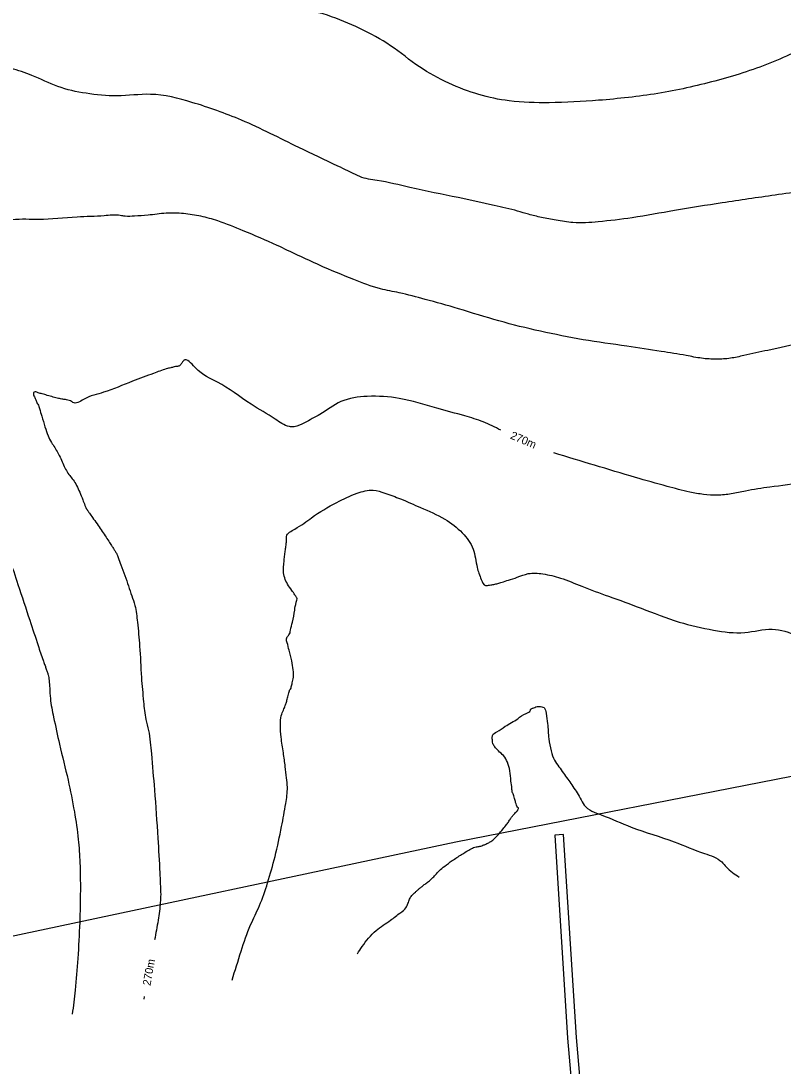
# Model space of a CAD drawing. Extents: x -478495 to -472450, y -1118050 to -1113745.
# Drawn here: x -474676.7 to -474505.2, y -1116040.4 to -1115805.4 of the extents above; entities that cross this region are included whole.
import ezdxf

# ---------------------------------------------------------------- set-up
doc = ezdxf.new("R2010")
doc.units = 0
for name, color, linetype in [('hranice kú', 7, 'Continuous'), ('ObPÚ', 7, 'Continuous'), ('vodní plochy', 7, 'Continuous'), ('Vrstevnice_hlavni', 7, 'Continuous'), ('Vrstevnice_popis', 7, 'Continuous'), ('Vrstevnice_vedlejsi', 7, 'Continuous')]:
    doc.layers.add(name, color=color, linetype=linetype)

msp = doc.modelspace()

# ---------------------------------------------------------------- linework, layer by layer
at = {"layer": 'hranice kú'}
for p, q in [((-474578.81, -1115989.99), (-474391.43, -1115953.34)), ((-474709.58, -1116017.74), (-474578.81, -1115989.99))]:
    msp.add_line(p, q, dxfattribs=at)
at = {"layer": 'ObPÚ'}
for p, q in [((-474578.81, -1115989.99), (-474391.43, -1115953.34)), ((-474709.58, -1116017.74), (-474578.81, -1115989.99))]:
    msp.add_line(p, q, dxfattribs=at)
at = {"layer": 'vodní plochy'}
msp.add_line((-474554.56, -1115988.35), (-474556.55, -1115988.48), dxfattribs=at)
for points in [[(-474556.55, -1115988.48), (-474553.66, -1116034.16)], [(-474529.71, -1116266.12), (-474535.81, -1116214.06), (-474540.64, -1116167.48), (-474541.99, -1116137.5), (-474545.48, -1116104.98), (-474551.66, -1116034.01), (-474554.56, -1115988.35)], [(-474553.66, -1116034.16), (-474547.47, -1116105.17), (-474543.99, -1116137.65), (-474542.64, -1116167.63), (-474537.8, -1116214.28), (-474531.83, -1116265.2)]]:
    msp.add_lwpolyline(points, dxfattribs=at)
at = {"layer": 'Vrstevnice_hlavni'}
msp.add_line((-474648.99, -1116025.33), (-474648.89, -1116024.79), dxfattribs=at)
for points in [[(-474353.29, -1115910.1), (-474357.76, -1115907), (-474363.58, -1115903.14), (-474372.98, -1115896.97), (-474385.95, -1115888.49), (-474394.72, -1115882.73), (-474399.29, -1115879.71), (-474399.64, -1115879.42), (-474399.97, -1115879.33), (-474400.28, -1115879.42), (-474400.55, -1115879.71), (-474401.05, -1115880.31), (-474401.76, -1115881.21), (-474402.7, -1115882.42), (-474405.92, -1115887.27), (-474411.43, -1115895.76), (-474419.22, -1115907.88), (-474425.86, -1115917.02), (-474431.34, -1115923.19), (-474435.67, -1115926.38), (-474439.9, -1115927.44), (-474444.04, -1115926.38), (-474448.08, -1115923.19), (-474453.87, -1115919.56), (-474461.41, -1115915.5), (-474470.71, -1115911.01), (-474480.28, -1115908.45), (-474490.15, -1115907.82), (-474500.29, -1115909.13), (-474508.12, -1115910.22), (-474513.62, -1115911.09), (-474516.81, -1115911.75), (-474519.96, -1115912.01), (-474523.07, -1115911.86), (-474526.15, -1115911.32), (-474531.26, -1115910.04), (-474538.41, -1115908.02), (-474556.79, -1115902.51)], [(-474568.71, -1115897.41), (-474572.64, -1115895.54), (-474576.77, -1115894.2), (-474583.07, -1115892.45), (-474591.54, -1115890.28), (-474598.74, -1115889.8), (-474604.7, -1115890.99), (-474609.4, -1115893.85), (-474612.89, -1115895.74), (-474615.18, -1115896.66), (-474616.27, -1115896.61), (-474619.51, -1115894.92), (-474624.89, -1115891.58), (-474632.42, -1115886.61), (-474637.48, -1115883.33), (-474640.07, -1115881.75), (-474640.18, -1115881.86), (-474640.33, -1115882.05), (-474640.51, -1115882.31), (-474640.73, -1115882.66), (-474640.99, -1115882.9), (-474641.29, -1115883.04), (-474641.64, -1115883.07), (-474642.2, -1115883.18), (-474642.99, -1115883.37), (-474643.99, -1115883.63), (-474646.84, -1115884.63), (-474651.55, -1115886.39), (-474658.1, -1115888.89), (-474662.59, -1115890.48), (-474664.99, -1115891.16), (-474665.32, -1115890.92), (-474665.81, -1115890.73), (-474666.45, -1115890.57), (-474667.26, -1115890.45), (-474668.24, -1115890.25), (-474669.42, -1115889.95), (-474670.78, -1115889.57), (-474671.92, -1115889.24), (-474672.82, -1115888.99), (-474673.5, -1115888.79), (-474673.84, -1115888.94), (-474673.83, -1115889.44), (-474673.49, -1115890.29), (-474673.22, -1115890.94), (-474673, -1115891.37), (-474672.85, -1115891.59), (-474672.51, -1115892.55), (-474671.99, -1115894.24), (-474671.28, -1115896.67), (-474670.56, -1115898.65), (-474669.83, -1115900.18), (-474669.09, -1115901.27), (-474668.4, -1115902.47), (-474667.74, -1115903.78), (-474667.12, -1115905.21), (-474666.45, -1115906.49), (-474665.72, -1115907.61), (-474664.93, -1115908.58), (-474664.18, -1115909.82), (-474663.46, -1115911.32), (-474662.77, -1115913.09), (-474662.29, -1115914.31), (-474662.01, -1115914.99), (-474661.93, -1115915.12), (-474661.85, -1115915.24), (-474661.77, -1115915.36), (-474661.68, -1115915.48), (-474661.29, -1115916.04), (-474660.58, -1115917.04), (-474659.56, -1115918.47), (-474658.61, -1115919.84), (-474657.73, -1115921.15), (-474656.92, -1115922.4), (-474656.31, -1115923.34), (-474655.89, -1115923.98), (-474655.67, -1115924.32), (-474655.48, -1115924.61), (-474655.32, -1115924.88), (-474655.2, -1115925.09), (-474654.82, -1115926.04), (-474654.19, -1115927.71), (-474653.3, -1115930.11), (-474652.48, -1115932.43), (-474651.74, -1115934.66), (-474651.05, -1115936.81), (-474650.47, -1115940.58), (-474649.97, -1115945.97), (-474649.57, -1115952.99), (-474649.1, -1115958.48), (-474648.57, -1115962.46), (-474647.98, -1115964.93), (-474647.34, -1115970.19), (-474646.64, -1115978.26), (-474645.89, -1115989.13), (-474645.42, -1115996.98), (-474645.23, -1116001.81)], [(-474645.23, -1116001.81), (-474645.33, -1116003.61), (-474645.52, -1116005.55), (-474645.82, -1116007.62), (-474646.61, -1116012.03)]]:
    msp.add_spline(points, degree=3, dxfattribs=at)
at = {"layer": 'Vrstevnice_vedlejsi'}
for points in [[(-474307.19, -1115713.78), (-474307.99, -1115713.91), (-474308.82, -1115714.23), (-474309.67, -1115714.76), (-474310.56, -1115715.49), (-474311.65, -1115716.4), (-474312.94, -1115717.49), (-474314.45, -1115718.76), (-474316.08, -1115719.99), (-474317.84, -1115721.19), (-474319.73, -1115722.34), (-474321.15, -1115723.17), (-474322.12, -1115723.66), (-474322.64, -1115723.82), (-474323.08, -1115724.06), (-474323.44, -1115724.38), (-474323.73, -1115724.79), (-474326.4, -1115725.43), (-474331.46, -1115726.31), (-474338.91, -1115727.42), (-474345.39, -1115728.27), (-474350.91, -1115728.88), (-474355.45, -1115729.23), (-474360.11, -1115731.22), (-474364.87, -1115734.85), (-474369.73, -1115740.13), (-474374.74, -1115745.26), (-474379.87, -1115750.27), (-474385.15, -1115755.13), (-474389.04, -1115759.06), (-474391.56, -1115762.05), (-474392.7, -1115764.11), (-474394.15, -1115766.16), (-474395.89, -1115768.21), (-474397.95, -1115770.27), (-474400.91, -1115771.86), (-474404.79, -1115773), (-474409.58, -1115773.69), (-474415.62, -1115774.92), (-474422.92, -1115776.7), (-474431.46, -1115779.03), (-474438.67, -1115781.14), (-474444.56, -1115783.02), (-474449.11, -1115784.68), (-474454.43, -1115787.3), (-474460.5, -1115790.89), (-474467.34, -1115795.44), (-474472.23, -1115798.79), (-474475.19, -1115800.92), (-474476.22, -1115801.84), (-474477.2, -1115802.56), (-474478.16, -1115803.09), (-474479.08, -1115803.42), (-474480.18, -1115803.71), (-474481.46, -1115803.96), (-474482.92, -1115804.16), (-474487.85, -1115806.05), (-474496.25, -1115809.62), (-474508.12, -1115814.87), (-474520.49, -1115818.88), (-474533.33, -1115821.67), (-474546.67, -1115823.22), (-474557.83, -1115823.77), (-474566.83, -1115823.34), (-474573.65, -1115821.91), (-474580.37, -1115819.36), (-474586.99, -1115815.71), (-474593.49, -1115810.94), (-474600.4, -1115807.07), (-474607.71, -1115804.11), (-474615.41, -1115802.05), (-474622.42, -1115800.42), (-474628.74, -1115799.21), (-474634.37, -1115798.42), (-474641.58, -1115797.17), (-474650.36, -1115795.45), (-474660.72, -1115793.27), (-474668.62, -1115791.35), (-474674.06, -1115789.7), (-474677.03, -1115788.3), (-474679.71, -1115787.15), (-474682.1, -1115786.24), (-474684.19, -1115785.57), (-474688.05, -1115785.01), (-474693.67, -1115784.55), (-474701.05, -1115784.2), (-474706.07, -1115783.9), (-474708.75, -1115783.67), (-474709.08, -1115783.5), (-474709.77, -1115783.43), (-474710.83, -1115783.48), (-474712.26, -1115783.64), (-474713.28, -1115783.74), (-474713.9, -1115783.78), (-474714.11, -1115783.76), (-474714.62, -1115783.69), (-474715.41, -1115783.58)], [(-474405.5, -1115810.13), (-474411, -1115813.31), (-474417.27, -1115815.96), (-474424.33, -1115818.06), (-474432.17, -1115819.63), (-474438.49, -1115821.66), (-474443.3, -1115824.16), (-474446.6, -1115827.13), (-474451.88, -1115830.21), (-474459.14, -1115833.4), (-474468.37, -1115836.7), (-474474.71, -1115838.99), (-474478.15, -1115840.26), (-474478.69, -1115840.51), (-474479.14, -1115840.68), (-474479.49, -1115840.76), (-474479.74, -1115840.76), (-474480.02, -1115840.77), (-474480.32, -1115840.82), (-474480.64, -1115840.89), (-474485.19, -1115841.53), (-474493.97, -1115842.75), (-474506.98, -1115844.55), (-474518.85, -1115846.29), (-474529.57, -1115847.99), (-474539.14, -1115849.64), (-474546.77, -1115850.55), (-474552.47, -1115850.73), (-474556.24, -1115850.16), (-474559.57, -1115849.54), (-474562.46, -1115848.86), (-474564.92, -1115848.12), (-474570.19, -1115846.87), (-474578.26, -1115845.11), (-474589.13, -1115842.83), (-474596.51, -1115841.25), (-474600.4, -1115840.37), (-474600.8, -1115840.19), (-474605.37, -1115838.01), (-474614.13, -1115833.84), (-474627.07, -1115827.68), (-474638.2, -1115823.69), (-474647.53, -1115821.88), (-474655.07, -1115822.24), (-474662.02, -1115821.65), (-474668.4, -1115820.11), (-474674.2, -1115817.62), (-474678.98, -1115816.02), (-474682.76, -1115815.29), (-474685.51, -1115815.44), (-474687.88, -1115815.58), (-474689.86, -1115815.71), (-474691.46, -1115815.83), (-474693.42, -1115816), (-474695.74, -1115816.22), (-474698.43, -1115816.49), (-474700.66, -1115816.67), (-474702.41, -1115816.78), (-474703.71, -1115816.82), (-474704.75, -1115816.93), (-474705.55, -1115817.14), (-474706.1, -1115817.42), (-474706.5, -1115817.63), (-474706.77, -1115817.77), (-474706.9, -1115817.82), (-474707.07, -1115817.94), (-474707.29, -1115818.12), (-474707.55, -1115818.35), (-474707.99, -1115818.69), (-474708.63, -1115819.11), (-474709.46, -1115819.64), (-474710.11, -1115819.92), (-474710.58, -1115819.96), (-474710.88, -1115819.75), (-474711.12, -1115819.56), (-474711.3, -1115819.42), (-474711.41, -1115819.3), (-474711.61, -1115818.94), (-474711.92, -1115818.33), (-474712.31, -1115817.48), (-474712.71, -1115816.64), (-474713.12, -1115815.83), (-474713.53, -1115815.03), (-474713.9, -1115814.35), (-474714.23, -1115813.79), (-474714.54, -1115813.33), (-474714.81, -1115812.86), (-474715.06, -1115812.38), (-474715.28, -1115811.88), (-474715.67, -1115811.15), (-474716.23, -1115810.18), (-474716.96, -1115808.98), (-474717.48, -1115808.13), (-474717.78, -1115807.64), (-474717.86, -1115807.51), (-474717.98, -1115807.32), (-474718.11, -1115807.08)], [(-474209.03, -1115951.03), (-474211.31, -1115950.17), (-474219.22, -1115947.13), (-474229.61, -1115943.09), (-474237.42, -1115939.16), (-474242.66, -1115935.36), (-474245.32, -1115931.67), (-474248.92, -1115928.32), (-474253.48, -1115925.32), (-474258.98, -1115922.66), (-474263.71, -1115920.22), (-474267.65, -1115917.99), (-474270.81, -1115915.98), (-474273.59, -1115914.5), (-474275.98, -1115913.57), (-474277.99, -1115913.16), (-474281.05, -1115911.98), (-474285.17, -1115910.01), (-474290.34, -1115907.25), (-474296.51, -1115904.05), (-474303.67, -1115900.41), (-474311.84, -1115896.33), (-474318.15, -1115893.11), (-474322.6, -1115890.76), (-474325.2, -1115889.28), (-474328.18, -1115887.42), (-474331.54, -1115885.2), (-474335.3, -1115882.6), (-474339.21, -1115879.96), (-474343.3, -1115877.27), (-474347.55, -1115874.53), (-474351.29, -1115870.13), (-474354.53, -1115864.06), (-474357.27, -1115856.31), (-474360.52, -1115850.2), (-474364.29, -1115845.71), (-474368.57, -1115842.86), (-474374.44, -1115840.32), (-474381.91, -1115838.09), (-474390.95, -1115836.19), (-474398.08, -1115835.56), (-474403.29, -1115836.19), (-474406.58, -1115838.09), (-474412.12, -1115842.87), (-474419.91, -1115850.52), (-474429.96, -1115861.04), (-474437.29, -1115868.36), (-474441.91, -1115872.47), (-474443.81, -1115873.38), (-474448.89, -1115873.86), (-474457.14, -1115873.93), (-474468.57, -1115873.57), (-474479.64, -1115874.09), (-474490.34, -1115875.48), (-474500.68, -1115877.74), (-474508.57, -1115879.45), (-474514.01, -1115880.62), (-474517.01, -1115881.23), (-474520.17, -1115881.44), (-474523.49, -1115881.23), (-474526.98, -1115880.62), (-474532.59, -1115879.71), (-474540.32, -1115878.52), (-474550.16, -1115877.05), (-474559.76, -1115875.15), (-474569.12, -1115872.83), (-474578.24, -1115870.1), (-474585.73, -1115867.98), (-474591.58, -1115866.48)], [(-474591.58, -1115866.48), (-474595.79, -1115865.6), (-474601.77, -1115863.53), (-474609.52, -1115860.29), (-474619.05, -1115855.86), (-474626.67, -1115852.55), (-474632.38, -1115850.36), (-474636.19, -1115849.29), (-474640.08, -1115848.71), (-474644.04, -1115848.63), (-474648.09, -1115849.05), (-474651.15, -1115849.27), (-474653.22, -1115849.3), (-474654.32, -1115849.13), (-474657.93, -1115849.19), (-474664.05, -1115849.49), (-474672.69, -1115850.01), (-474678.68, -1115850.13), (-474682.03, -1115849.83), (-474682.72, -1115849.12), (-474683.59, -1115848.65), (-474684.63, -1115848.42), (-474685.83, -1115848.44), (-474687.09, -1115848.46), (-474688.41, -1115848.49), (-474689.78, -1115848.53), (-474691.08, -1115848.57), (-474692.3, -1115848.61), (-474693.44, -1115848.66), (-474694.22, -1115848.69), (-474694.61, -1115848.7), (-474694.63, -1115848.7), (-474694.65, -1115848.69), (-474694.66, -1115848.69), (-474694.67, -1115848.68), (-474694.81, -1115848.54), (-474695.07, -1115848.28), (-474695.46, -1115847.89), (-474696.14, -1115847.64), (-474697.11, -1115847.54), (-474698.36, -1115847.58), (-474699.5, -1115847.6), (-474700.52, -1115847.58), (-474701.42, -1115847.54), (-474702.23, -1115847.47), (-474702.96, -1115847.38), (-474703.6, -1115847.26), (-474704.71, -1115847.62), (-474706.28, -1115848.45), (-474708.32, -1115849.77), (-474709.74, -1115850.69), (-474710.54, -1115851.23), (-474710.73, -1115851.39), (-474710.86, -1115851.5), (-474710.94, -1115851.58), (-474710.97, -1115851.62), (-474711.2, -1115851.74), (-474711.65, -1115851.93), (-474712.29, -1115852.2), (-474712.88, -1115854.06), (-474713.41, -1115857.53), (-474713.88, -1115862.59), (-474714.27, -1115866.83), (-474714.59, -1115870.24), (-474714.83, -1115872.82), (-474714.93, -1115874.8), (-474714.89, -1115876.18), (-474714.7, -1115876.96), (-474714.49, -1115877.67), (-474714.27, -1115878.32), (-474714.04, -1115878.91), (-474713.67, -1115879.51), (-474713.18, -1115880.13), (-474712.56, -1115880.76), (-474710.65, -1115882.69), (-474707.44, -1115885.94), (-474702.93, -1115890.49), (-474699.42, -1115893.99), (-474696.92, -1115896.42), (-474695.42, -1115897.79), (-474693.03, -1115901.02), (-474689.76, -1115906.11), (-474685.59, -1115913.05), (-474682.66, -1115918.14), (-474680.95, -1115921.36), (-474680.48, -1115922.72), (-474679.28, -1115926.31), (-474677.35, -1115932.12), (-474674.7, -1115940.16), (-474672.82, -1115945.83), (-474671.7, -1115949.15), (-474671.35, -1115950.09), (-474671.05, -1115950.95), (-474670.78, -1115951.74), (-474670.56, -1115952.44), (-474670.37, -1115953.67), (-474670.21, -1115955.43)], [(-474629.16, -1116021.12), (-474627.14, -1116014.55), (-474625, -1116008.66), (-474623.01, -1116004.33), (-474621.17, -1115999.2), (-474619.51, -1115993.27), (-474618.02, -1115986.54), (-474617.09, -1115981.36), (-474616.72, -1115977.71), (-474616.91, -1115975.61), (-474617.21, -1115973.04), (-474617.62, -1115969.98), (-474618.13, -1115966.44), (-474618.29, -1115963.66), (-474618.11, -1115961.63), (-474617.59, -1115960.34), (-474617.2, -1115959.33), (-474616.94, -1115958.59), (-474616.81, -1115958.12), (-474616.68, -1115957.61), (-474616.55, -1115957.06), (-474616.41, -1115956.47), (-474616.27, -1115956.03), (-474616.14, -1115955.75), (-474616.01, -1115955.62), (-474615.84, -1115955.12), (-474615.62, -1115954.23), (-474615.37, -1115952.97), (-474615.41, -1115951.32), (-474615.73, -1115949.29), (-474616.35, -1115946.88), (-474616.75, -1115945.22), (-474616.92, -1115944.31), (-474616.88, -1115944.15), (-474616.77, -1115943.95), (-474616.6, -1115943.72), (-474616.36, -1115943.46), (-474616.03, -1115942.4), (-474615.6, -1115940.55), (-474615.07, -1115937.91), (-474614.73, -1115936.11), (-474614.6, -1115935.14), (-474614.67, -1115935.01), (-474615.04, -1115934.44), (-474615.72, -1115933.45), (-474616.7, -1115932.02), (-474617.32, -1115930.59), (-474617.6, -1115929.14), (-474617.53, -1115927.68), (-474617.42, -1115926.35), (-474617.28, -1115925.14), (-474617.11, -1115924.05), (-474616.99, -1115923.05), (-474616.92, -1115922.15), (-474616.91, -1115921.33), (-474615.02, -1115919.64), (-474611.26, -1115917.08), (-474605.63, -1115913.66), (-474601.01, -1115911.59), (-474597.41, -1115910.89), (-474594.81, -1115911.55), (-474591.26, -1115912.86), (-474586.76, -1115914.81), (-474581.29, -1115917.41), (-474577.35, -1115920.51), (-474574.92, -1115924.14), (-474574.01, -1115928.27), (-474573.09, -1115931.01), (-474572.16, -1115932.33), (-474571.21, -1115932.24), (-474570.27, -1115932.09), (-474569.34, -1115931.88)], [(-474569.34, -1115931.88), (-474568.42, -1115931.59), (-474566.98, -1115931.13), (-474565, -1115930.49), (-474562.5, -1115929.67), (-474559.24, -1115929.73), (-474555.23, -1115930.67), (-474550.45, -1115932.5), (-474544.42, -1115934.75), (-474537.12, -1115937.44), (-474528.56, -1115940.55), (-474520.79, -1115942.37), (-474513.8, -1115942.91), (-474507.6, -1115942.16), (-474502.01, -1115943.72), (-474497.03, -1115947.6), (-474492.66, -1115953.8), (-474489.31, -1115958.42), (-474486.99, -1115961.47), (-474485.69, -1115962.93), (-474484.34, -1115964.25), (-474482.93, -1115965.4), (-474481.47, -1115966.41), (-474479.67, -1115967.07), (-474477.53, -1115967.41), (-474475.06, -1115967.41), (-474469.79, -1115968.48), (-474461.73, -1115970.63), (-474450.86, -1115973.85), (-474440.49, -1115975.41), (-474430.62, -1115975.33), (-474421.24, -1115973.59), (-474413.66, -1115972.82), (-474407.9, -1115973.02), (-474403.95, -1115974.18), (-474399.42, -1115975.28)], [(-474670.21, -1115955.43), (-474670.07, -1115957.71), (-474669.34, -1115961.92), (-474668.01, -1115968.05), (-474666.08, -1115976.1), (-474664.67, -1115983.23), (-474663.78, -1115989.43), (-474663.42, -1115994.72), (-474663.32, -1116000.94), (-474663.47, -1116008.1), (-474663.89, -1116016.21), (-474664.48, -1116023.35), (-474665.14, -1116028.76)], [(-474570.6, -1115966.38), (-474570.55, -1115966.04), (-474569.59, -1115965.25), (-474567.7, -1115964), (-474564.88, -1115962.29), (-474563, -1115961.1), (-474562.05, -1115960.44), (-474562.03, -1115960.3), (-474561.97, -1115960.18), (-474561.86, -1115960.08), (-474561.72, -1115960), (-474561.45, -1115959.89), (-474561.05, -1115959.75), (-474560.53, -1115959.58), (-474560, -1115959.53), (-474559.48, -1115959.6), (-474558.96, -1115959.8), (-474558.52, -1115961.07), (-474558.17, -1115963.4), (-474557.89, -1115966.79), (-474557.38, -1115969.54), (-474556.61, -1115971.64), (-474555.6, -1115973.09), (-474554.61, -1115974.5), (-474553.64, -1115975.86), (-474552.7, -1115977.19), (-474551.76, -1115978.61), (-474550.83, -1115980.13), (-474549.91, -1115981.74), (-474546.08, -1115983.92), (-474539.33, -1115986.67), (-474529.66, -1115989.99), (-474522.87, -1115992.6), (-474518.96, -1115994.5), (-474517.91, -1115995.68), (-474515.08, -1115997.91)], [(-474600.96, -1116015.14), (-474599.89, -1116013.55), (-474596.75, -1116009.91), (-474593.5, -1116007.61), (-474591.26, -1116005.91), (-474590.03, -1116004.81), (-474589.8, -1116004.32), (-474589.59, -1116003.84), (-474589.4, -1116003.36), (-474589.23, -1116002.9), (-474588.99, -1116002.46), (-474588.68, -1116002.05), (-474588.31, -1116001.67), (-474587.9, -1116001.28), (-474587.46, -1116000.88), (-474586.99, -1116000.47), (-474586.42, -1116000.01), (-474585.75, -1115999.48), (-474584.98, -1115998.91), (-474584.19, -1115998.22), (-474583.39, -1115997.42), (-474582.58, -1115996.51), (-474581.32, -1115995.44), (-474579.63, -1115994.21), (-474577.51, -1115992.81), (-474575.9, -1115991.84), (-474574.81, -1115991.28), (-474574.23, -1115991.14), (-474573.76, -1115991.03), (-474573.4, -1115990.96), (-474573.15, -1115990.92), (-474572.71, -1115990.76), (-474572.06, -1115990.48), (-474571.21, -1115990.08), (-474570.29, -1115989.38), (-474569.28, -1115988.38), (-474568.19, -1115987.08), (-474567.38, -1115986.07), (-474566.85, -1115985.35), (-474566.6, -1115984.93), (-474566.37, -1115984.58), (-474566.17, -1115984.29), (-474565.98, -1115984.06), (-474565.72, -1115983.77), (-474565.38, -1115983.41), (-474564.96, -1115982.98), (-474564.75, -1115982.62), (-474564.74, -1115982.35), (-474564.93, -1115982.15), (-474565.14, -1115981.74), (-474565.35, -1115981.12), (-474565.59, -1115980.27), (-474565.78, -1115979.63), (-474565.93, -1115979.18), (-474566.04, -1115978.93), (-474566.2, -1115977.98), (-474566.41, -1115976.34), (-474566.66, -1115974.01), (-474567.22, -1115972.09), (-474568.08, -1115970.6), (-474569.24, -1115969.54), (-474570.04, -1115968.63), (-474570.48, -1115967.89), (-474570.56, -1115967.3), (-474570.6, -1115966.8), (-474570.6, -1115966.38)]]:
    msp.add_spline(points, degree=3, dxfattribs=at)

# ---------------------------------------------------------------- texts
at = {"layer": 'Vrstevnice_popis'}
for height, rotation, p in [(1.8, 336.8301, (-474567.32, -1115898.98)), (1.799, 79.8457, (-474647.67, -1116023.09))]:
    msp.add_text(' 270m ', height=height, rotation=rotation, dxfattribs=at).set_placement(p)

doc.saveas('drawing.dxf')
